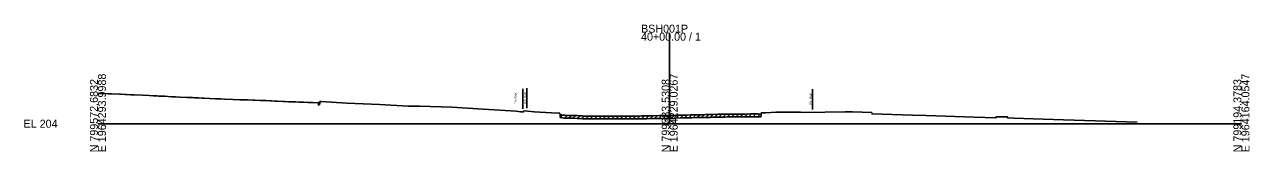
# Model space of a CAD drawing. Extents: x -26 to 1403, y -10 to 19587.
# Drawn here: x 974.3 to 1402.8, y 3990.3 to 4034.6 of the extents above; entities that cross this region are included whole.
import ezdxf

# ---------------------------------------------------------------- set-up
doc = ezdxf.new("R2010")
doc.units = 0
for name, color, linetype in [('Default', 7, 'Continuous'), ('RD_GPK_XS_Cell', 7, 'Continuous'), ('RD_XS_ExGround', 7, 'Continuous'), ('RD_XS_ExPaveRet', 7, 'Continuous'), ('RD_XS_ExRW', 7, 'Continuous'), ('RD_XS_TX_Elev_EX', 7, 'Continuous')]:
    doc.layers.add(name, color=color, linetype=linetype)

msp = doc.modelspace()

# ---------------------------------------------------------------- linework, layer by layer
at = {"layer": 'RD_GPK_XS_Cell'}
for p, q in [((1200, 4000), (1200, 4031.79)), ((1000, 4000), (1200, 4000)), ((1200, 4000), (1400, 4000))]:
    msp.add_line(p, q, dxfattribs=at)
at = {"layer": 'RD_XS_ExGround'}
msp.add_lwpolyline([(1000, 4010.6), (1002.09, 4010.51), (1003.61, 4010.46), (1004.74, 4010.41), (1007.52, 4010.3), (1007.95, 4010.29), (1009.52, 4010.22), (1010.02, 4010.2), (1011.52, 4010.13), (1012.65, 4010.08), (1015.61, 4009.94), (1017.93, 4009.83), (1019.31, 4009.76), (1020.57, 4009.7), (1021.27, 4009.67), (1023.44, 4009.56), (1025.86, 4009.43), (1027.09, 4009.37), (1028.5, 4009.31), (1031.14, 4009.17), (1033.12, 4009.1), (1033.8, 4009.06), (1035.21, 4009), (1036.42, 4008.94), (1037.03, 4008.91), (1039.08, 4008.81), (1040.98, 4008.72), (1041.71, 4008.68), (1042.96, 4008.63), (1044.36, 4008.55), (1047.2, 4008.45), (1049.65, 4008.38), (1051.27, 4008.33), (1052.29, 4008.3), (1054.18, 4008.24), (1054.94, 4008.21), (1056.7, 4008.14), (1057.58, 4008.11), (1058.69, 4008.06), (1060.24, 4008), (1060.67, 4007.98), (1061.93, 4007.92), (1062.87, 4007.87), (1064.64, 4007.79), (1065.47, 4007.75), (1066.82, 4007.69), (1068.05, 4007.64), (1069.07, 4007.6), (1070.33, 4007.54), (1071.5, 4007.5), (1071.99, 4007.48), (1073.4, 4007.45), (1074.6, 4007.42), (1075.11, 4007.41), (1077.15, 4007.34), (1077.64, 4007.77), (1078.04, 4007.75), (1087.05, 4007.17), (1098.45, 4006.71), (1108.5, 4006.18), (1112.51, 4006.11), (1123.77, 4005.74), (1134.77, 4005.08), (1146.3, 4004.35), (1147.79, 4004.19), (1148.89, 4004.19), (1148.96, 4004.48), (1150.34, 4004.34), (1152.57, 4004.15), (1158.62, 4003.8), (1161.21, 4003.67), (1161.53, 4003.66), (1161.67, 4003.2), (1162.04, 4003.13), (1162.94, 4002.95), (1163.28, 4002.93), (1163.68, 4002.91), (1164.08, 4002.91), (1165.96, 4002.89), (1167.67, 4002.83), (1168.57, 4002.8), (1169.55, 4002.72), (1170.2, 4002.69), (1170.78, 4002.68), (1172.33, 4002.66), (1172.86, 4002.66), (1173.94, 4002.65), (1175.51, 4002.65), (1178.15, 4002.65), (1178.45, 4002.66), (1180.19, 4002.67), (1180.78, 4002.67), (1181.98, 4002.66), (1183.41, 4002.65), (1184.11, 4002.65), (1186.16, 4002.67), (1188.68, 4002.69), (1189.99, 4002.71), (1191.33, 4002.73), (1191.97, 4002.74), (1194.06, 4002.78), (1196.6, 4002.82), (1197.86, 4002.84), (1199.28, 4002.86), (1200, 4002.87), (1201.55, 4002.91), (1202.17, 4002.93), (1204.58, 4003), (1205.77, 4003.03), (1207.23, 4003.07), (1207.76, 4003.09), (1209.29, 4003.11), (1209.86, 4003.12), (1211.68, 4003.15), (1212.51, 4003.17), (1214.18, 4003.21), (1215.14, 4003.23), (1216.95, 4003.28), (1217.78, 4003.3), (1219, 4003.34), (1219.45, 4003.34), (1220.4, 4003.36), (1222.23, 4003.36), (1223.04, 4003.36), (1223.44, 4003.36), (1224.6, 4003.37), (1225.71, 4003.37), (1226.29, 4003.38), (1228.33, 4003.39), (1230, 4003.4), (1230.59, 4003.4), (1230.92, 4003.39), (1231.54, 4003.38), (1231.89, 4003.36), (1231.99, 4003.37), (1232.09, 4003.82), (1233.58, 4003.85), (1237.16, 4004.01), (1245.81, 4003.98), (1247.3, 4003.97), (1261.41, 4004.15), (1263.17, 4004.14), (1263.93, 4004.11), (1270.7, 4003.86), (1270.8, 4003.41), (1284.91, 4003.03), (1289.71, 4002.9), (1306.48, 4002.27), (1314.15, 4002), (1314.25, 4002.44), (1317.65, 4002.44), (1318.13, 4002.45), (1318.23, 4002), (1320.49, 4001.91), (1327.16, 4001.66), (1337.83, 4001.3), (1363.49, 4000.58)], dxfattribs=at)
at = {"layer": 'RD_XS_ExPaveRet'}
for p, q in [((1077.15, 4006.34), (1077.15, 4007.34)), ((1077.64, 4007.77), (1077.64, 4006.77)), ((1077.15, 4006.34), (1077.64, 4006.77)), ((1077.15, 4006.34), (1077.15, 4006.34)), ((1161.67, 4002.2), (1161.67, 4003.2)), ((1161.67, 4002.2), (1162.51, 4003.04)), ((1163.17, 4001.94), (1164.14, 4002.91)), ((1164.67, 4001.9), (1165.66, 4002.89)), ((1166.17, 4001.88), (1167.14, 4002.85)), ((1167.67, 4001.83), (1168.64, 4002.79)), ((1169.17, 4001.75), (1170.12, 4002.69)), ((1170.67, 4001.68), (1171.66, 4002.67)), ((1172.17, 4001.66), (1173.17, 4002.65)), ((1173.67, 4001.65), (1174.67, 4002.65)), ((1175.17, 4001.65), (1176.17, 4002.65)), ((1176.67, 4001.65), (1177.68, 4002.65)), ((1178.17, 4001.65), (1179.18, 4002.66)), ((1179.67, 4001.66), (1180.68, 4002.67)), ((1181.17, 4001.67), (1182.17, 4002.66)), ((1182.67, 4001.66), (1183.67, 4002.65)), ((1184.17, 4001.65), (1185.18, 4002.66)), ((1185.67, 4001.66), (1186.68, 4002.67)), ((1187.17, 4001.68), (1188.18, 4002.69)), ((1188.67, 4001.69), (1189.69, 4002.7)), ((1190.17, 4001.71), (1191.19, 4002.73)), ((1191.67, 4001.74), (1192.69, 4002.76)), ((1193.17, 4001.76), (1194.19, 4002.78)), ((1194.67, 4001.79), (1195.69, 4002.81)), ((1196.17, 4001.81), (1197.19, 4002.83)), ((1197.67, 4001.84), (1198.69, 4002.85)), ((1199.17, 4001.85), (1200.19, 4002.87)), ((1200.67, 4001.89), (1201.7, 4002.91)), ((1202.17, 4001.93), (1203.21, 4002.96)), ((1203.67, 4001.97), (1204.71, 4003)), ((1205.17, 4002.02), (1206.2, 4003.04)), ((1206.67, 4002.06), (1207.7, 4003.09)), ((1208.17, 4002.09), (1209.19, 4003.11)), ((1209.67, 4002.12), (1210.69, 4003.14)), ((1211.17, 4002.14), (1212.19, 4003.16)), ((1212.67, 4002.17), (1213.7, 4003.2)), ((1214.17, 4002.21), (1215.2, 4003.23)), ((1215.67, 4002.25), (1216.7, 4003.27)), ((1217.17, 4002.28), (1218.2, 4003.31)), ((1218.67, 4002.33), (1219.69, 4003.35)), ((1220.17, 4002.35), (1221.18, 4003.36)), ((1221.67, 4002.36), (1222.68, 4003.36)), ((1223.17, 4002.36), (1224.18, 4003.37)), ((1224.67, 4002.37), (1225.68, 4003.37)), ((1226.17, 4002.37), (1227.18, 4003.38)), ((1227.67, 4002.38), (1228.68, 4003.39)), ((1229.17, 4002.39), (1230.18, 4003.4)), ((1230.67, 4002.4), (1231.65, 4003.37)), ((1231.89, 4002.36), (1231.99, 4002.59)), ((1231.99, 4003.59), (1231.99, 4002.59)), ((1161.67, 4002.2), (1162.04, 4002.13)), ((1162.04, 4002.13), (1162.94, 4001.95)), ((1162.94, 4001.95), (1163.28, 4001.93)), ((1163.28, 4001.93), (1163.68, 4001.91)), ((1163.68, 4001.91), (1164.08, 4001.91)), ((1164.08, 4001.91), (1165.96, 4001.89)), ((1165.96, 4001.89), (1167.67, 4001.83)), ((1167.67, 4001.83), (1168.57, 4001.8)), ((1168.57, 4001.8), (1169.55, 4001.72)), ((1169.55, 4001.72), (1170.2, 4001.69)), ((1170.2, 4001.69), (1170.78, 4001.68)), ((1170.78, 4001.68), (1172.33, 4001.66)), ((1172.33, 4001.66), (1172.86, 4001.66)), ((1172.86, 4001.66), (1173.94, 4001.65)), ((1173.94, 4001.65), (1175.51, 4001.65)), ((1175.51, 4001.65), (1178.15, 4001.65)), ((1178.15, 4001.65), (1178.45, 4001.66)), ((1178.45, 4001.66), (1180.19, 4001.67)), ((1180.19, 4001.67), (1180.78, 4001.67)), ((1180.78, 4001.67), (1181.98, 4001.66)), ((1181.98, 4001.66), (1183.41, 4001.65)), ((1183.41, 4001.65), (1184.11, 4001.65)), ((1184.11, 4001.65), (1186.16, 4001.67)), ((1186.16, 4001.67), (1188.68, 4001.69)), ((1188.68, 4001.69), (1189.99, 4001.71)), ((1189.99, 4001.71), (1191.33, 4001.73)), ((1191.33, 4001.73), (1191.97, 4001.74)), ((1191.97, 4001.74), (1194.06, 4001.78)), ((1194.06, 4001.78), (1196.6, 4001.82)), ((1196.6, 4001.82), (1197.86, 4001.84)), ((1197.86, 4001.84), (1199.28, 4001.86)), ((1199.28, 4001.86), (1200, 4001.87)), ((1200, 4001.87), (1201.55, 4001.91)), ((1201.55, 4001.91), (1202.17, 4001.93)), ((1202.17, 4001.93), (1204.58, 4002)), ((1204.58, 4002), (1205.77, 4002.03)), ((1205.77, 4002.03), (1207.23, 4002.07)), ((1207.23, 4002.07), (1207.76, 4002.09)), ((1207.76, 4002.09), (1209.29, 4002.11)), ((1209.29, 4002.11), (1209.86, 4002.12)), ((1209.86, 4002.12), (1211.68, 4002.15)), ((1211.68, 4002.15), (1212.51, 4002.17)), ((1212.51, 4002.17), (1214.18, 4002.21)), ((1214.18, 4002.21), (1215.14, 4002.23)), ((1215.14, 4002.23), (1216.95, 4002.28)), ((1216.95, 4002.28), (1217.78, 4002.3)), ((1217.78, 4002.3), (1219, 4002.34)), ((1219, 4002.34), (1219.45, 4002.34)), ((1219.45, 4002.34), (1220.4, 4002.36)), ((1220.4, 4002.36), (1222.23, 4002.36)), ((1222.23, 4002.36), (1223.04, 4002.36)), ((1223.04, 4002.36), (1223.44, 4002.36)), ((1223.44, 4002.36), (1224.6, 4002.37)), ((1224.6, 4002.37), (1225.71, 4002.37)), ((1225.71, 4002.37), (1226.29, 4002.38)), ((1226.29, 4002.38), (1228.33, 4002.39)), ((1228.33, 4002.39), (1230, 4002.4)), ((1230, 4002.4), (1230.59, 4002.4)), ((1230.59, 4002.4), (1230.92, 4002.39)), ((1230.92, 4002.39), (1231.54, 4002.38)), ((1231.54, 4002.38), (1231.89, 4002.36))]:
    msp.add_line(p, q, dxfattribs=at)
at = {"layer": 'RD_XS_ExRW'}
for p, q in [((1148.61, 4005.19), (1148.61, 4012.19)), ((1150, 4005.37), (1150, 4012.37)), ((1250, 4005.01), (1250, 4012.01))]:
    msp.add_line(p, q, dxfattribs=at)

# ---------------------------------------------------------------- texts
at = {"layer": 'Default'}
msp.add_text('-', height=0.0001, dxfattribs=at).set_placement((1000, 4000))
at = {"layer": 'RD_GPK_XS_Cell'}
for s, p in [('BSH001P', (1190, 4031.79)), ('40+00.00 / 1', (1190, 4028.99)), ('EL 204', (974, 3998.6))]:
    msp.add_text(s, height=2.8, dxfattribs=at).set_placement(p)
for s, p in [('N 799572.6832', (1000, 3990)), ('E 1964293.9988', (1002.8, 3990)), ('N 799383.5308', (1200, 3990)), ('E 1964229.0267', (1202.8, 3990)), ('N 799194.3783', (1400, 3990)), ('E 1964164.0547', (1402.8, 3990))]:
    msp.add_text(s, height=2.8, rotation=90, dxfattribs=at).set_placement(p)
at = {"layer": 'RD_XS_ExRW'}
for p in [(1146.53, 4006.86), (1149.75, 4007.04), (1249.75, 4006.68)]:
    msp.add_text('EX. R/W ', height=0.75, rotation=90, dxfattribs=at).set_placement(p)
at = {"layer": 'RD_XS_TX_Elev_EX'}
msp.add_text('206.87', height=1, dxfattribs=at).set_placement((1197.96, 4000.37))

doc.saveas('drawing.dxf')
